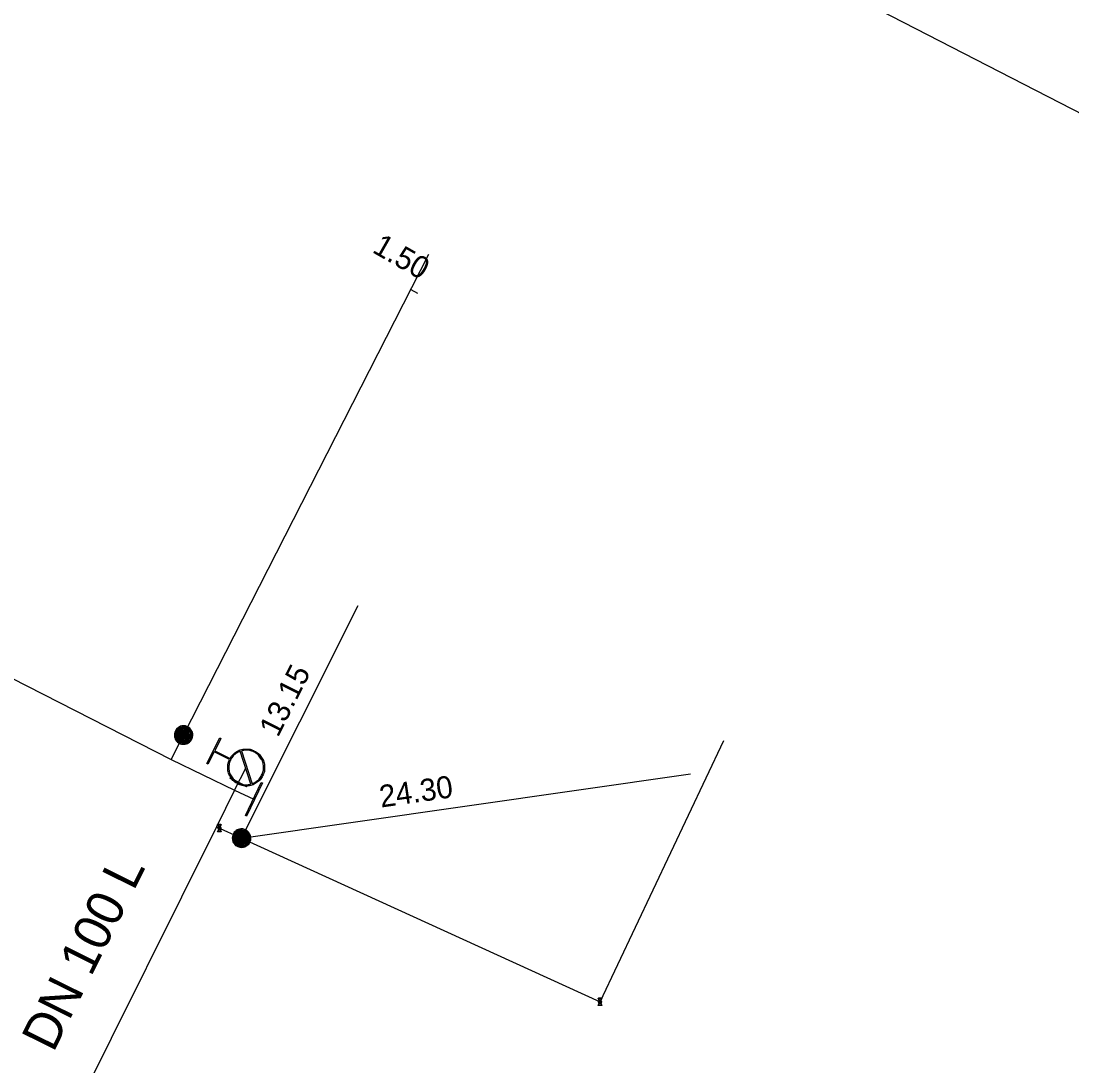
# Model space of a CAD drawing. Extents: x -820257 to -819974, y -1070894 to -1070484.
# Drawn here: x -820109.2 to -820052, y -1070634.2 to -1070577.4 of the extents above; entities that cross this region are included whole.
import ezdxf

# ---------------------------------------------------------------- set-up
doc = ezdxf.new("R2010")
doc.units = 0
for name, color, linetype in [('Hyd-odbočka', 7, 'Continuous'), ('Hyd-šoupě', 7, 'Continuous'), ('Hydrant', 7, 'Continuous'), ('Lomový bod vodovodu', 7, 'Continuous'), ('Oměrka vodovodu', 7, 'Continuous'), ('Oměrka-text', 7, 'Continuous'), ('Přípojka vodovodu', 7, 'Continuous'), ('Přípojkový uzávěr', 7, 'Continuous'), ('Roz-řad', 7, 'Continuous'), ('Roz-řad-popis základní', 7, 'Continuous'), ('Řad-šoupě', 7, 'Continuous')]:
    doc.layers.add(name, color=color, linetype=linetype)

msp = doc.modelspace()

# ---------------------------------------------------------------- linework, layer by layer
at = {"layer": 'Hyd-odbočka'}
msp.add_line((-820097.577, -1070619.176), (-820096.948, -1070617.946), dxfattribs=at)
at = {"layer": 'Hyd-šoupě'}
msp.add_lwpolyline([(-820097.802, -1070618.517), (-820096.912, -1070618.972), (-820096.926, -1070619), (-820097.816, -1070618.545), (-820097.802, -1070618.517)], dxfattribs=at)
at = {"layer": 'Hydrant'}
for points in [[(-820097.853, -1070617.519), (-820098.687, -1070617.092), (-820099.029, -1070617.76), (-820099.084, -1070617.732), (-820098.373, -1070616.34), (-820098.318, -1070616.369), (-820098.659, -1070617.037), (-820097.824, -1070617.463)], [(-820096.688, -1070618.849), (-820097.266, -1070617.062)], [(-820097.208, -1070617.043), (-820096.628, -1070618.831)]]:
    msp.add_lwpolyline(points, dxfattribs=at)
for points in [[(-820097.824, -1070617.463), (-820097.71, -1070617.256), (-820097.5, -1070617.111), (-820097.276, -1070616.958), (-820097.001, -1070616.947), (-820096.726, -1070616.936), (-820096.493, -1070617.056), (-820096.261, -1070617.174), (-820096.109, -1070617.4), (-820095.957, -1070617.625), (-820095.948, -1070617.898), (-820095.939, -1070618.17), (-820096.057, -1070618.401), (-820096.176, -1070618.632), (-820096.401, -1070618.785), (-820096.627, -1070618.937), (-820096.899, -1070618.946), (-820097.172, -1070618.955), (-820097.403, -1070618.836), (-820097.636, -1070618.717), (-820097.789, -1070618.488), (-820097.941, -1070618.259), (-820097.947, -1070617.988), (-820097.954, -1070617.735), (-820097.853, -1070617.519)], [(-820097.266, -1070617.062), (-820097.371, -1070617.1), (-820097.465, -1070617.164), (-820097.675, -1070617.309), (-820097.783, -1070617.519), (-820097.89, -1070617.73), (-820097.885, -1070617.985), (-820097.879, -1070618.24), (-820097.736, -1070618.454), (-820097.594, -1070618.669), (-820097.374, -1070618.781), (-820097.157, -1070618.892), (-820096.902, -1070618.882), (-820096.791, -1070618.879), (-820096.688, -1070618.849)], [(-820096.628, -1070618.831), (-820096.528, -1070618.794), (-820096.437, -1070618.731), (-820096.224, -1070618.59), (-820096.113, -1070618.373), (-820096.002, -1070618.155), (-820096.011, -1070617.9), (-820096.019, -1070617.644), (-820096.162, -1070617.433), (-820096.304, -1070617.222), (-820096.521, -1070617.111), (-820096.74, -1070616.999), (-820096.998, -1070617.01), (-820097.108, -1070617.015), (-820097.208, -1070617.043)]]:
    msp.add_open_spline(points, degree=3, dxfattribs=at)
at = {"layer": 'Lomový bod vodovodu'}
for points in [[(-820098.438, -1070621.176), (-820098.5, -1070621.04), (-820098.3, -1070621.04), (-820098.363, -1070621.176)], [(-820098.378, -1070621.169), (-820098.324, -1070621.053), (-820098.478, -1070621.053), (-820098.423, -1070621.169)], [(-820098.432, -1070621.293), (-820098.408, -1070621.24), (-820098.432, -1070621.187)], [(-820098.418, -1070621.18), (-820098.4, -1070621.218), (-820098.383, -1070621.18)], [(-820098.368, -1070621.187), (-820098.392, -1070621.24), (-820098.368, -1070621.293)], [(-820098.363, -1070621.304), (-820098.3, -1070621.44), (-820098.5, -1070621.44), (-820098.438, -1070621.304)], [(-820098.423, -1070621.311), (-820098.478, -1070621.428), (-820098.324, -1070621.428), (-820098.378, -1070621.311)], [(-820098.383, -1070621.3), (-820098.4, -1070621.262), (-820098.418, -1070621.3)], [(-820077.748, -1070630.616), (-820077.81, -1070630.48), (-820077.61, -1070630.48), (-820077.673, -1070630.616)], [(-820077.673, -1070630.744), (-820077.61, -1070630.88), (-820077.81, -1070630.88), (-820077.748, -1070630.744)], [(-820077.688, -1070630.609), (-820077.634, -1070630.493), (-820077.788, -1070630.493), (-820077.733, -1070630.609)], [(-820077.733, -1070630.751), (-820077.788, -1070630.868), (-820077.634, -1070630.868), (-820077.688, -1070630.751)], [(-820077.742, -1070630.733), (-820077.718, -1070630.68), (-820077.742, -1070630.627)], [(-820077.728, -1070630.62), (-820077.71, -1070630.658), (-820077.693, -1070630.62)], [(-820077.693, -1070630.74), (-820077.71, -1070630.702), (-820077.728, -1070630.74)], [(-820077.678, -1070630.627), (-820077.702, -1070630.68), (-820077.678, -1070630.733)]]:
    msp.add_lwpolyline(points, dxfattribs=at)
for points in [[(-820098.438, -1070621.304), (-820098.455, -1070621.295), (-820098.465, -1070621.277), (-820098.475, -1070621.26), (-820098.475, -1070621.24), (-820098.475, -1070621.22), (-820098.465, -1070621.203), (-820098.455, -1070621.185), (-820098.438, -1070621.176)], [(-820098.432, -1070621.187), (-820098.446, -1070621.195), (-820098.454, -1070621.209), (-820098.462, -1070621.224), (-820098.462, -1070621.24), (-820098.462, -1070621.256), (-820098.454, -1070621.271), (-820098.446, -1070621.285), (-820098.432, -1070621.293)], [(-820098.423, -1070621.169), (-820098.412, -1070621.165), (-820098.4, -1070621.165), (-820098.389, -1070621.165), (-820098.378, -1070621.169)], [(-820098.383, -1070621.18), (-820098.391, -1070621.178), (-820098.4, -1070621.178), (-820098.409, -1070621.178), (-820098.418, -1070621.18)], [(-820098.368, -1070621.293), (-820098.354, -1070621.285), (-820098.346, -1070621.271), (-820098.338, -1070621.256), (-820098.338, -1070621.24), (-820098.338, -1070621.224), (-820098.346, -1070621.209), (-820098.354, -1070621.195), (-820098.368, -1070621.187)], [(-820098.363, -1070621.176), (-820098.345, -1070621.185), (-820098.335, -1070621.203), (-820098.325, -1070621.22), (-820098.325, -1070621.24), (-820098.325, -1070621.26), (-820098.335, -1070621.277), (-820098.345, -1070621.295), (-820098.363, -1070621.304)], [(-820098.378, -1070621.311), (-820098.388, -1070621.315), (-820098.4, -1070621.315), (-820098.412, -1070621.315), (-820098.423, -1070621.311)], [(-820098.418, -1070621.3), (-820098.409, -1070621.302), (-820098.4, -1070621.302), (-820098.391, -1070621.302), (-820098.383, -1070621.3)], [(-820077.748, -1070630.744), (-820077.765, -1070630.735), (-820077.775, -1070630.717), (-820077.785, -1070630.7), (-820077.785, -1070630.68), (-820077.785, -1070630.66), (-820077.775, -1070630.643), (-820077.765, -1070630.625), (-820077.748, -1070630.616)], [(-820077.742, -1070630.627), (-820077.756, -1070630.635), (-820077.764, -1070630.649), (-820077.772, -1070630.664), (-820077.772, -1070630.68), (-820077.772, -1070630.696), (-820077.764, -1070630.711), (-820077.756, -1070630.725), (-820077.742, -1070630.733)], [(-820077.733, -1070630.609), (-820077.722, -1070630.605), (-820077.71, -1070630.605), (-820077.699, -1070630.605), (-820077.688, -1070630.609)], [(-820077.688, -1070630.751), (-820077.698, -1070630.755), (-820077.71, -1070630.755), (-820077.722, -1070630.755), (-820077.733, -1070630.751)], [(-820077.693, -1070630.62), (-820077.701, -1070630.618), (-820077.71, -1070630.618), (-820077.719, -1070630.618), (-820077.728, -1070630.62)], [(-820077.728, -1070630.74), (-820077.719, -1070630.742), (-820077.71, -1070630.742), (-820077.701, -1070630.742), (-820077.693, -1070630.74)], [(-820077.678, -1070630.733), (-820077.664, -1070630.725), (-820077.656, -1070630.711), (-820077.648, -1070630.696), (-820077.648, -1070630.68), (-820077.648, -1070630.664), (-820077.656, -1070630.649), (-820077.664, -1070630.635), (-820077.678, -1070630.627)], [(-820077.673, -1070630.616), (-820077.655, -1070630.625), (-820077.645, -1070630.643), (-820077.635, -1070630.66), (-820077.635, -1070630.68), (-820077.635, -1070630.7), (-820077.645, -1070630.717), (-820077.655, -1070630.735), (-820077.673, -1070630.744)]]:
    msp.add_open_spline(points, degree=3, dxfattribs=at)
at = {"layer": 'Oměrka vodovodu'}
for p, q in [((-820087.989, -1070591.967), (-820087.638, -1070592.168)), ((-820097.201, -1070621.787), (-820090.85, -1070609.148)), ((-820097.201, -1070621.787), (-820072.793, -1070618.29))]:
    msp.add_line(p, q, dxfattribs=at)
at = {"layer": 'Přípojka vodovodu'}
for points in [[(-820101.033, -1070617.521), (-820100.351, -1070616.185), (-820087.011, -1070590.052)], [(-820098.566, -1070621.164), (-820097.201, -1070621.787), (-820077.71, -1070630.68), (-820070.969, -1070616.479)]]:
    msp.add_lwpolyline(points, dxfattribs=at)
at = {"layer": 'Přípojkový uzávěr'}
for points in [[(-820100.797, -1070615.958), (-820100.739, -1070615.846), (-820100.627, -1070615.769), (-820100.516, -1070615.692), (-820100.378, -1070615.686), (-820100.24, -1070615.681), (-820100.123, -1070615.74), (-820100.008, -1070615.799), (-820099.932, -1070615.912), (-820099.856, -1070616.025), (-820099.851, -1070616.161), (-820099.847, -1070616.297), (-820099.906, -1070616.413), (-820099.965, -1070616.528), (-820100.078, -1070616.604), (-820100.19, -1070616.681), (-820100.326, -1070616.685), (-820100.462, -1070616.69), (-820100.578, -1070616.631), (-820100.694, -1070616.571), (-820100.771, -1070616.457), (-820100.848, -1070616.342), (-820100.851, -1070616.207), (-820100.854, -1070616.071), (-820100.797, -1070615.958)], [(-820100.755, -1070615.98), (-820100.807, -1070616.082), (-820100.804, -1070616.205), (-820100.801, -1070616.328), (-820100.732, -1070616.431), (-820100.662, -1070616.535), (-820100.557, -1070616.589), (-820100.452, -1070616.643), (-820100.329, -1070616.639), (-820100.206, -1070616.634), (-820100.103, -1070616.565), (-820100.001, -1070616.496), (-820099.948, -1070616.392), (-820099.894, -1070616.287), (-820099.898, -1070616.163), (-820099.902, -1070616.039), (-820099.971, -1070615.937), (-820100.04, -1070615.835), (-820100.145, -1070615.782), (-820100.25, -1070615.728), (-820100.375, -1070615.733), (-820100.501, -1070615.738), (-820100.602, -1070615.808), (-820100.703, -1070615.878), (-820100.755, -1070615.98)], [(-820100.724, -1070615.995), (-820100.676, -1070615.901), (-820100.583, -1070615.837), (-820100.489, -1070615.772), (-820100.374, -1070615.767), (-820100.258, -1070615.762), (-820100.16, -1070615.812), (-820100.063, -1070615.862), (-820099.999, -1070615.956), (-820099.936, -1070616.05), (-820099.932, -1070616.165), (-820099.928, -1070616.279), (-820099.978, -1070616.376), (-820100.027, -1070616.473), (-820100.122, -1070616.537), (-820100.217, -1070616.601), (-820100.33, -1070616.605), (-820100.444, -1070616.608), (-820100.541, -1070616.559), (-820100.639, -1070616.509), (-820100.703, -1070616.413), (-820100.767, -1070616.317), (-820100.77, -1070616.203), (-820100.772, -1070616.089), (-820100.724, -1070615.995)], [(-820100.685, -1070616.016), (-820100.756, -1070616.155), (-820100.708, -1070616.302), (-820100.66, -1070616.449), (-820100.521, -1070616.52), (-820100.383, -1070616.59), (-820100.235, -1070616.542), (-820100.088, -1070616.494), (-820100.017, -1070616.357), (-820099.946, -1070616.218), (-820099.994, -1070616.07), (-820100.042, -1070615.922), (-820100.18, -1070615.852), (-820100.319, -1070615.781), (-820100.466, -1070615.828), (-820100.614, -1070615.875), (-820100.685, -1070616.016)], [(-820100.645, -1070616.037), (-820100.582, -1070615.914), (-820100.453, -1070615.873), (-820100.324, -1070615.832), (-820100.203, -1070615.894), (-820100.082, -1070615.955), (-820100.04, -1070616.085), (-820099.998, -1070616.214), (-820100.06, -1070616.335), (-820100.122, -1070616.457), (-820100.251, -1070616.498), (-820100.38, -1070616.54), (-820100.502, -1070616.478), (-820100.623, -1070616.416), (-820100.665, -1070616.287), (-820100.707, -1070616.158), (-820100.645, -1070616.037)], [(-820100.609, -1070616.055), (-820100.664, -1070616.162), (-820100.627, -1070616.275), (-820100.59, -1070616.388), (-820100.484, -1070616.443), (-820100.377, -1070616.497), (-820100.263, -1070616.461), (-820100.15, -1070616.424), (-820100.095, -1070616.317), (-820100.041, -1070616.21), (-820100.078, -1070616.097), (-820100.115, -1070615.983), (-820100.221, -1070615.929), (-820100.328, -1070615.874), (-820100.441, -1070615.911), (-820100.555, -1070615.947), (-820100.609, -1070616.055)], [(-820100.574, -1070616.072), (-820100.526, -1070615.979), (-820100.428, -1070615.947), (-820100.33, -1070615.916), (-820100.237, -1070615.963), (-820100.145, -1070616.01), (-820100.113, -1070616.108), (-820100.081, -1070616.207), (-820100.129, -1070616.299), (-820100.175, -1070616.391), (-820100.274, -1070616.423), (-820100.372, -1070616.455), (-820100.464, -1070616.408), (-820100.557, -1070616.361), (-820100.589, -1070616.263), (-820100.621, -1070616.165), (-820100.574, -1070616.072)], [(-820100.533, -1070616.093), (-820100.571, -1070616.168), (-820100.545, -1070616.248), (-820100.519, -1070616.328), (-820100.444, -1070616.366), (-820100.369, -1070616.405), (-820100.289, -1070616.379), (-820100.209, -1070616.353), (-820100.171, -1070616.278), (-820100.133, -1070616.203), (-820100.158, -1070616.123), (-820100.184, -1070616.043), (-820100.259, -1070616.005), (-820100.335, -1070615.966), (-820100.414, -1070615.992), (-820100.494, -1070616.018), (-820100.533, -1070616.093)], [(-820100.502, -1070616.109), (-820100.47, -1070616.046), (-820100.404, -1070616.025), (-820100.338, -1070616.004), (-820100.275, -1070616.036), (-820100.212, -1070616.067), (-820100.191, -1070616.134), (-820100.17, -1070616.2), (-820100.202, -1070616.262), (-820100.234, -1070616.325), (-820100.3, -1070616.346), (-820100.366, -1070616.368), (-820100.428, -1070616.336), (-820100.491, -1070616.304), (-820100.512, -1070616.238), (-820100.534, -1070616.172), (-820100.502, -1070616.109)], [(-820100.463, -1070616.129), (-820100.486, -1070616.175), (-820100.47, -1070616.224), (-820100.454, -1070616.273), (-820100.408, -1070616.297), (-820100.362, -1070616.32), (-820100.312, -1070616.304), (-820100.263, -1070616.288), (-820100.24, -1070616.243), (-820100.216, -1070616.196), (-820100.232, -1070616.147), (-820100.248, -1070616.098), (-820100.294, -1070616.074), (-820100.34, -1070616.05), (-820100.389, -1070616.066), (-820100.439, -1070616.082), (-820100.463, -1070616.129)], [(-820100.421, -1070616.15), (-820100.406, -1070616.121), (-820100.375, -1070616.111), (-820100.345, -1070616.101), (-820100.316, -1070616.116), (-820100.287, -1070616.131), (-820100.277, -1070616.161), (-820100.267, -1070616.192), (-820100.282, -1070616.221), (-820100.296, -1070616.25), (-820100.327, -1070616.26), (-820100.358, -1070616.27), (-820100.387, -1070616.255), (-820100.416, -1070616.24), (-820100.426, -1070616.21), (-820100.435, -1070616.179), (-820100.421, -1070616.15)], [(-820100.393, -1070616.164), (-820100.402, -1070616.182), (-820100.396, -1070616.2), (-820100.39, -1070616.218), (-820100.373, -1070616.228), (-820100.355, -1070616.236), (-820100.337, -1070616.23), (-820100.318, -1070616.224), (-820100.309, -1070616.207), (-820100.3, -1070616.189), (-820100.306, -1070616.171), (-820100.313, -1070616.153), (-820100.33, -1070616.144), (-820100.348, -1070616.135), (-820100.366, -1070616.141), (-820100.384, -1070616.147), (-820100.393, -1070616.164)], [(-820096.993, -1070621.332), (-820096.879, -1070621.384), (-820096.797, -1070621.492), (-820096.715, -1070621.6), (-820096.703, -1070621.738), (-820096.692, -1070621.876), (-820096.746, -1070621.995), (-820096.8, -1070622.113), (-820096.909, -1070622.194), (-820097.018, -1070622.274), (-820097.154, -1070622.285), (-820097.29, -1070622.295), (-820097.409, -1070622.241), (-820097.526, -1070622.188), (-820097.607, -1070622.078), (-820097.688, -1070621.969), (-820097.699, -1070621.833), (-820097.71, -1070621.698), (-820097.656, -1070621.58), (-820097.601, -1070621.461), (-820097.49, -1070621.379), (-820097.379, -1070621.297), (-820097.244, -1070621.288), (-820097.109, -1070621.279), (-820096.993, -1070621.332)], [(-820097.013, -1070621.374), (-820097.117, -1070621.327), (-820097.24, -1070621.335), (-820097.363, -1070621.343), (-820097.463, -1070621.417), (-820097.564, -1070621.491), (-820097.613, -1070621.599), (-820097.662, -1070621.706), (-820097.652, -1070621.829), (-820097.643, -1070621.951), (-820097.569, -1070622.051), (-820097.496, -1070622.15), (-820097.389, -1070622.199), (-820097.282, -1070622.248), (-820097.158, -1070622.238), (-820097.035, -1070622.229), (-820096.936, -1070622.155), (-820096.837, -1070622.082), (-820096.789, -1070621.975), (-820096.739, -1070621.867), (-820096.75, -1070621.742), (-820096.761, -1070621.618), (-820096.835, -1070621.52), (-820096.909, -1070621.422), (-820097.013, -1070621.374)], [(-820097.027, -1070621.405), (-820096.931, -1070621.449), (-820096.862, -1070621.54), (-820096.794, -1070621.63), (-820096.784, -1070621.746), (-820096.774, -1070621.861), (-820096.82, -1070621.961), (-820096.865, -1070622.06), (-820096.956, -1070622.128), (-820097.047, -1070622.196), (-820097.161, -1070622.204), (-820097.275, -1070622.213), (-820097.375, -1070622.168), (-820097.474, -1070622.123), (-820097.542, -1070622.031), (-820097.61, -1070621.939), (-820097.618, -1070621.826), (-820097.627, -1070621.712), (-820097.582, -1070621.613), (-820097.536, -1070621.513), (-820097.443, -1070621.445), (-820097.35, -1070621.376), (-820097.237, -1070621.369), (-820097.123, -1070621.362), (-820097.027, -1070621.405)], [(-820097.046, -1070621.445), (-820097.188, -1070621.38), (-820097.333, -1070621.435), (-820097.477, -1070621.49), (-820097.542, -1070621.631), (-820097.606, -1070621.773), (-820097.552, -1070621.918), (-820097.497, -1070622.063), (-820097.357, -1070622.127), (-820097.215, -1070622.192), (-820097.07, -1070622.138), (-820096.924, -1070622.084), (-820096.86, -1070621.943), (-820096.795, -1070621.801), (-820096.849, -1070621.656), (-820096.902, -1070621.511), (-820097.046, -1070621.445)], [(-820097.065, -1070621.487), (-820096.94, -1070621.544), (-820096.893, -1070621.671), (-820096.846, -1070621.798), (-820096.903, -1070621.922), (-820096.959, -1070622.046), (-820097.086, -1070622.093), (-820097.213, -1070622.14), (-820097.337, -1070622.084), (-820097.462, -1070622.027), (-820097.509, -1070621.9), (-820097.556, -1070621.773), (-820097.5, -1070621.649), (-820097.443, -1070621.525), (-820097.316, -1070621.478), (-820097.189, -1070621.43), (-820097.065, -1070621.487)], [(-820097.081, -1070621.523), (-820097.191, -1070621.473), (-820097.302, -1070621.515), (-820097.414, -1070621.557), (-820097.464, -1070621.666), (-820097.513, -1070621.774), (-820097.472, -1070621.886), (-820097.43, -1070621.998), (-820097.321, -1070622.048), (-820097.212, -1070622.098), (-820097.1, -1070622.056), (-820096.988, -1070622.014), (-820096.939, -1070621.905), (-820096.889, -1070621.796), (-820096.93, -1070621.685), (-820096.972, -1070621.573), (-820097.081, -1070621.523)], [(-820097.097, -1070621.559), (-820097.002, -1070621.603), (-820096.966, -1070621.699), (-820096.93, -1070621.796), (-820096.973, -1070621.891), (-820097.016, -1070621.985), (-820097.113, -1070622.021), (-820097.21, -1070622.057), (-820097.305, -1070622.014), (-820097.399, -1070621.971), (-820097.435, -1070621.874), (-820097.471, -1070621.778), (-820097.428, -1070621.683), (-820097.385, -1070621.589), (-820097.289, -1070621.552), (-820097.192, -1070621.516), (-820097.097, -1070621.559)], [(-820097.116, -1070621.601), (-820097.193, -1070621.566), (-820097.272, -1070621.596), (-820097.351, -1070621.625), (-820097.386, -1070621.702), (-820097.421, -1070621.779), (-820097.391, -1070621.857), (-820097.362, -1070621.936), (-820097.285, -1070621.971), (-820097.209, -1070622.006), (-820097.13, -1070621.976), (-820097.051, -1070621.947), (-820097.016, -1070621.87), (-820096.981, -1070621.793), (-820097.01, -1070621.715), (-820097.04, -1070621.636), (-820097.116, -1070621.601)], [(-820097.131, -1070621.633), (-820097.067, -1070621.662), (-820097.043, -1070621.727), (-820097.018, -1070621.792), (-820097.048, -1070621.856), (-820097.077, -1070621.92), (-820097.142, -1070621.944), (-820097.207, -1070621.968), (-820097.271, -1070621.939), (-820097.335, -1070621.91), (-820097.359, -1070621.845), (-820097.383, -1070621.78), (-820097.354, -1070621.716), (-820097.325, -1070621.652), (-820097.26, -1070621.628), (-820097.195, -1070621.604), (-820097.131, -1070621.633)], [(-820097.149, -1070621.673), (-820097.196, -1070621.651), (-820097.245, -1070621.669), (-820097.293, -1070621.688), (-820097.314, -1070621.735), (-820097.336, -1070621.782), (-820097.318, -1070621.83), (-820097.3, -1070621.879), (-820097.253, -1070621.9), (-820097.205, -1070621.922), (-820097.157, -1070621.904), (-820097.108, -1070621.886), (-820097.087, -1070621.839), (-820097.065, -1070621.791), (-820097.083, -1070621.743), (-820097.101, -1070621.695), (-820097.149, -1070621.673)], [(-820097.169, -1070621.715), (-820097.138, -1070621.729), (-820097.127, -1070621.759), (-820097.116, -1070621.789), (-820097.13, -1070621.819), (-820097.143, -1070621.848), (-820097.173, -1070621.86), (-820097.203, -1070621.871), (-820097.233, -1070621.858), (-820097.263, -1070621.844), (-820097.274, -1070621.814), (-820097.285, -1070621.783), (-820097.272, -1070621.754), (-820097.258, -1070621.724), (-820097.228, -1070621.713), (-820097.198, -1070621.702), (-820097.169, -1070621.715)], [(-820097.182, -1070621.744), (-820097.199, -1070621.736), (-820097.217, -1070621.742), (-820097.235, -1070621.749), (-820097.244, -1070621.767), (-820097.252, -1070621.785), (-820097.245, -1070621.803), (-820097.238, -1070621.821), (-820097.22, -1070621.829), (-820097.202, -1070621.837), (-820097.184, -1070621.831), (-820097.166, -1070621.824), (-820097.158, -1070621.806), (-820097.15, -1070621.788), (-820097.157, -1070621.77), (-820097.163, -1070621.752), (-820097.182, -1070621.744)]]:
    msp.add_open_spline(points, degree=3, dxfattribs=at)
at = {"layer": 'Roz-řad'}
for p, q in [((-820110.178, -1070552.224), (-820031.976, -1070592.492)), ((-820097.577, -1070619.176), (-820096.528, -1070619.677))]:
    msp.add_line(p, q, dxfattribs=at)
for points in [[(-820170.782, -1070581.978), (-820165.379, -1070584.688), (-820101.033, -1070617.521), (-820097.577, -1070619.176)], [(-820097.577, -1070619.176), (-820098.566, -1070621.164), (-820106.194, -1070636.505)]]:
    msp.add_lwpolyline(points, dxfattribs=at)
at = {"layer": 'Řad-šoupě'}
msp.add_lwpolyline([(-820096.068, -1070618.787), (-820096.93, -1070620.592), (-820096.986, -1070620.565), (-820096.125, -1070618.76), (-820096.068, -1070618.787)], dxfattribs=at)

# ---------------------------------------------------------------- texts
at = {"layer": 'Oměrka-text'}
for s, rotation, p in [(' 1.50', 330.2024, (-820090.534, -1070589.696)), ('13.15', 63.3208, (-820095.222, -1070616.35)), ('24.30', 8.1534, (-820089.619, -1070620.126))]:
    msp.add_text(s, height=1.2, rotation=rotation, dxfattribs=at).set_placement(p)
at = {"layer": 'Roz-řad-popis základní'}
msp.add_text('DN 100 L', height=2, rotation=63.5607, dxfattribs=at).set_placement((-820107.435, -1070633.483))

doc.saveas('drawing.dxf')
